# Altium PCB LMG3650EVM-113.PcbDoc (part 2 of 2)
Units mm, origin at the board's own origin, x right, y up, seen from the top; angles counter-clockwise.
Board outline 76.61 x 43.92 mm, 4 copper layers (Top Layer, Signal Layer 1, Signal Layer 2, Bottom Layer), stack 0.688 mm thick; 100 components, 58 nets, 255 pads, 761 vias.
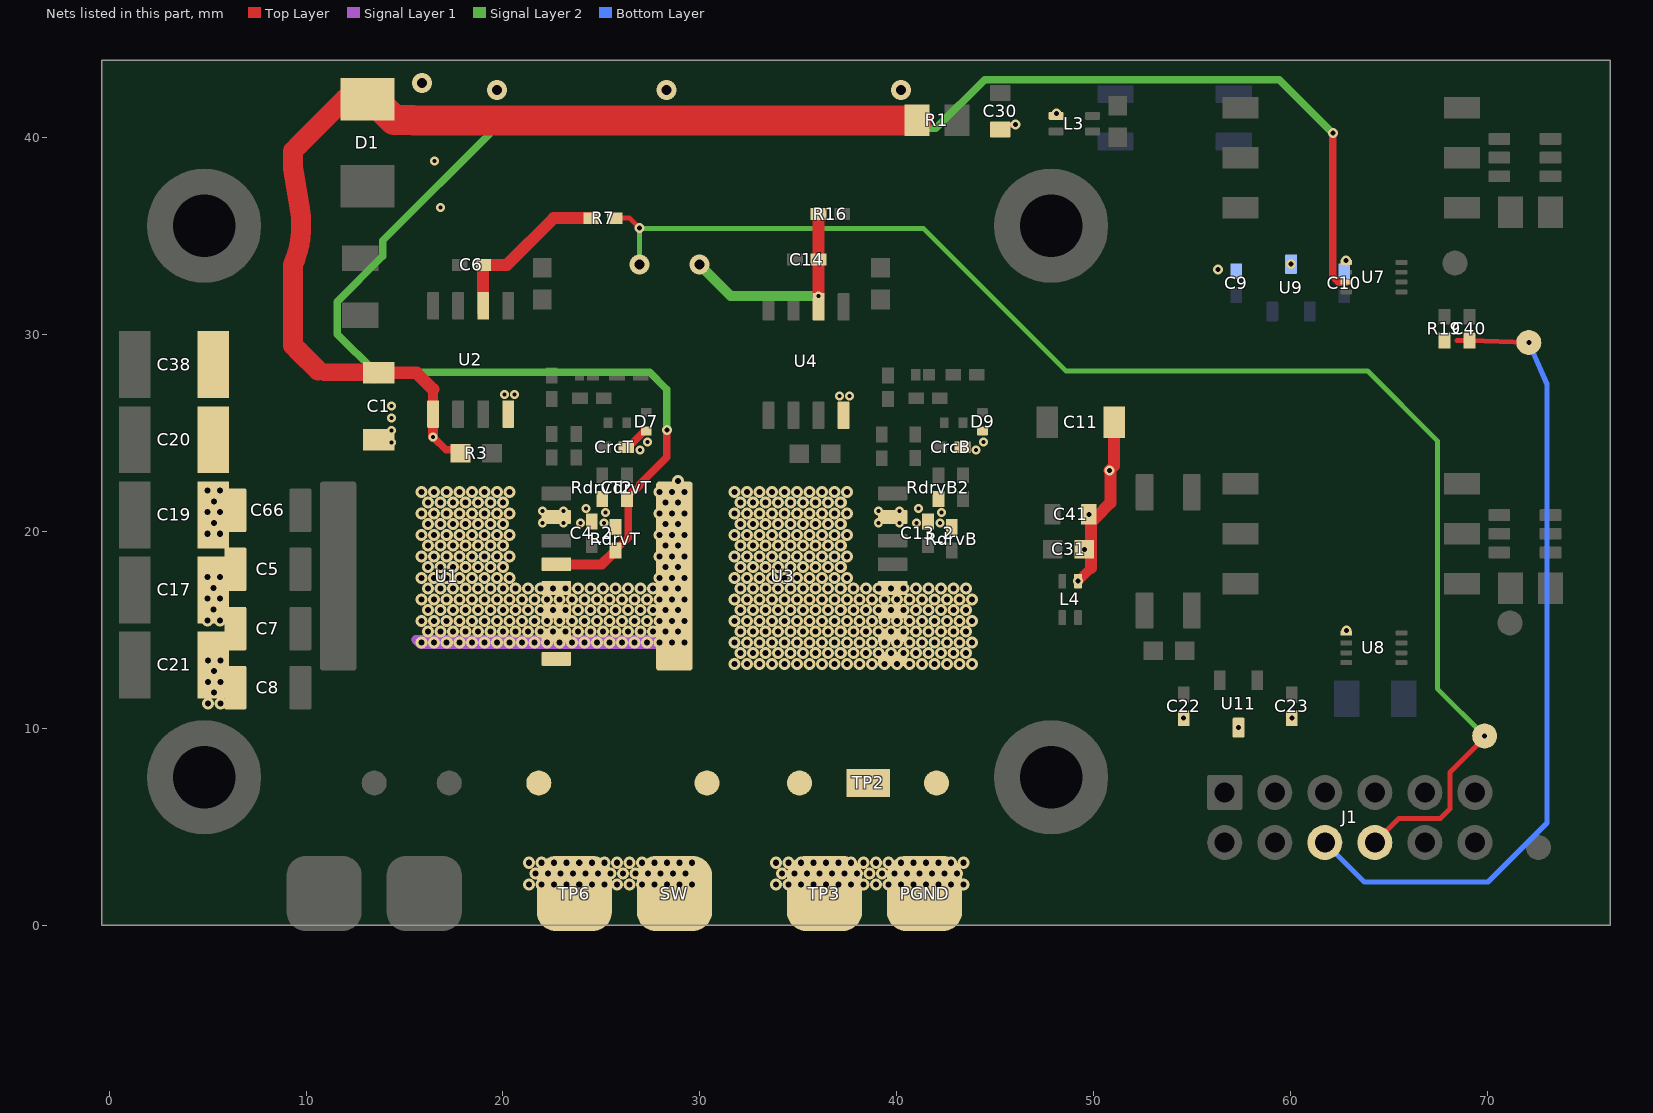
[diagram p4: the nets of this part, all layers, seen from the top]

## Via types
v1: diameter 0.61, hole 0.305, Top Layer to Bottom Layer, tented both sides, 665 vias
v2: diameter 0.508, hole 0.254, Top Layer to Bottom Layer, tented both sides, 47 vias
v3: diameter 0.457, hole 0.203, Top Layer to Bottom Layer, tented both sides, 41 vias
v4: diameter 1.016, hole 0.508, Top Layer to Bottom Layer, 8 vias

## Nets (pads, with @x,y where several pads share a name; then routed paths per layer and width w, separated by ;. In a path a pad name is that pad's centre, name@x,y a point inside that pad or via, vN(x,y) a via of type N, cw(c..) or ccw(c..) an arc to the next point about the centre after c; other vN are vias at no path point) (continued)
PGND: C5.1 C7.1 C8.1 C17.2 C19.2 C20.2 C21.2 C38.2 C66.1 pad.1@35.052,7.214 pad.1@42.012,7.214 PGND.1 TP2.1 TP3.1 U3.1 U3.2 U3.3 U3.4
  other v1: 33.85,2.071 34.485,2.071 35.12,2.071 35.755,2.071 36.39,2.071 37.025,2.071 37.66,2.071 38.295,2.071 38.93,2.071 39.565,2.071 40.2,2.071 40.835,2.071 41.47,2.071 42.105,2.071 42.74,2.071 43.375,2.071 34.167,2.617 34.802,2.617 35.437,2.617 36.072,2.617 36.707,2.617 37.342,2.617 37.977,2.617 38.612,2.617 39.247,2.617 39.882,2.617 40.517,2.617 41.152,2.617 41.787,2.617 42.422,2.617 43.057,2.617 33.85,3.163 34.485,3.163 35.12,3.163 35.755,3.163 36.39,3.163 37.025,3.163 37.66,3.163 38.295,3.163 38.93,3.163 39.565,3.163 40.2,3.163 40.835,3.163 41.47,3.163 42.105,3.163 42.74,3.163 43.375,3.163 5.015,11.257 5.65,11.257 5.333,11.804 5.015,12.35 5.65,12.35 5.333,12.896 31.75,13.259 32.385,13.259 33.02,13.259 33.655,13.259 34.29,13.259 34.925,13.259 35.56,13.259 36.195,13.259 36.83,13.259 37.465,13.259 38.1,13.259 38.735,13.259 39.37,13.259 40.005,13.259 40.64,13.259 41.275,13.259 41.91,13.259 42.545,13.259 43.18,13.259 43.815,13.259 5.015,13.442 5.65,13.442 32.067,13.805 32.703,13.805 33.337,13.805 33.972,13.805 34.608,13.805 35.242,13.805 35.877,13.805 36.512,13.805 37.148,13.805 37.782,13.805 38.417,13.805 39.052,13.805 39.688,13.805 40.322,13.805 40.957,13.805 41.593,13.805 42.227,13.805 42.862,13.805 43.497,13.805 31.75,14.351 32.385,14.351 33.02,14.351 33.655,14.351 34.29,14.351 34.925,14.351 35.56,14.351 36.195,14.351 36.83,14.351 37.465,14.351 38.1,14.351 38.735,14.351 39.37,14.351 40.005,14.351 40.64,14.351 41.275,14.351 41.91,14.351 42.545,14.351 43.18,14.351 43.815,14.351 32.067,14.897 32.703,14.897 33.337,14.897 33.972,14.897 34.608,14.897 35.242,14.897 35.877,14.897 36.512,14.897 37.148,14.897 37.782,14.897 38.417,14.897 39.052,14.897 39.688,14.897 40.322,14.897 40.957,14.897 41.593,14.897 42.227,14.897 42.862,14.897 43.497,14.897 31.75,15.443 32.385,15.443 33.02,15.443 33.655,15.443 34.29,15.443 34.925,15.443 35.56,15.443 36.195,15.443 36.83,15.443 37.465,15.443 38.1,15.443 38.735,15.443 39.37,15.443 40.005,15.443 40.64,15.443 41.275,15.443 41.91,15.443 42.545,15.443 43.18,15.443 43.815,15.443 4.987,15.475 5.622,15.475 32.067,15.989 32.703,15.989 33.337,15.989 33.972,15.989 34.608,15.989 35.242,15.989 35.877,15.989 36.512,15.989 37.148,15.989 37.782,15.989 38.417,15.989 39.052,15.989 39.688,15.989 40.322,15.989 40.957,15.989 41.593,15.989 42.227,15.989 42.862,15.989 43.497,15.989 5.305,16.021 31.75,16.535 32.385,16.535 33.02,16.535 33.655,16.535 34.29,16.535 34.925,16.535 35.56,16.535 36.195,16.535 36.83,16.535 37.465,16.535 38.1,16.535 38.735,16.535 39.37,16.535 40.005,16.535 40.64,16.535 41.275,16.535 41.91,16.535 42.545,16.535 43.18,16.535 43.815,16.535 4.987,16.567 5.622,16.567 32.067,17.081 32.703,17.081 33.337,17.081 33.972,17.081 34.608,17.081 35.242,17.081 35.877,17.081 36.512,17.081 37.148,17.081 37.782,17.081 38.417,17.081 39.052,17.081 39.688,17.081 40.322,17.081 40.957,17.081 41.593,17.081 42.227,17.081 42.862,17.081 43.497,17.081 5.305,17.113 31.75,17.628 32.385,17.628 33.02,17.628 33.655,17.628 34.29,17.628 34.925,17.628 35.56,17.628 36.195,17.628 36.83,17.628 37.465,17.628 4.987,17.659 5.622,17.659 32.067,18.174 32.703,18.174 33.337,18.174 33.972,18.174 34.608,18.174 35.242,18.174 35.877,18.174 36.512,18.174 37.148,18.174 31.75,18.72 32.385,18.72 33.02,18.72 33.655,18.72 34.29,18.72 34.925,18.72 35.56,18.72 36.195,18.72 36.83,18.72 37.465,18.72 32.067,19.266 32.703,19.266 33.337,19.266 33.972,19.266 34.608,19.266 35.242,19.266 35.877,19.266 36.512,19.266 37.148,19.266 31.75,19.812 32.385,19.812 33.02,19.812 33.655,19.812 34.29,19.812 34.925,19.812 35.56,19.812 36.195,19.812 36.83,19.812 37.465,19.812 5.004,19.866 5.639,19.866 32.067,20.358 32.703,20.358 33.337,20.358 33.972,20.358 34.608,20.358 35.242,20.358 35.877,20.358 36.512,20.358 37.148,20.358 5.321,20.412 31.75,20.904 32.385,20.904 33.02,20.904 33.655,20.904 34.29,20.904 34.925,20.904 35.56,20.904 36.195,20.904 36.83,20.904 37.465,20.904 5.004,20.958 5.639,20.958 32.067,21.45 32.703,21.45 33.337,21.45 33.972,21.45 34.608,21.45 35.242,21.45 35.877,21.45 36.512,21.45 37.148,21.45 5.321,21.504 31.75,21.996 32.385,21.996 33.02,21.996 33.655,21.996 34.29,21.996 34.925,21.996 35.56,21.996 36.195,21.996 36.83,21.996 37.465,21.996 5.004,22.05 5.639,22.05
PWM_H: C6.1 R7.2 U2.2 | length 8.9
  Top Layer w0.61: U2.2@18.994,31.101 18.994,33.51 20.197,33.51 22.574,35.887 R7.2@24.478,35.887
PWM_L: C14.2 R16.2 U4.2 | length 10.9
  Top Layer w0.61: v3(36.017,31.939) 36.017,35.077 36.022,35.077 R16.2@36.022,36.093
  Signal Layer 2 w0.508: v4(29.972,33.528) 31.561,31.939 v3(36.017,31.939)
S_PGND: C11.1 C13_2.2 C22.2 C23.2 C31.2 C41.2 CrcB.1 D9.2 L4.1 RdrvB2.1 RdrvB.1 U3.7 U4.8 U8.5 U11.3 | length 8.8
  Top Layer w0.483: v2(49.193,17.46) 49.859,18.126
  Top Layer w0.61: 49.859,18.126 49.859,20.461 50.086,20.688 50.837,21.439 v2@50.837,23.081 ; v2(50.798,23.081) 51.027,23.31 C11.1@51.027,25.527
  other v2: 57.343,10.027 54.559,10.5 60.046,10.5 62.811,14.961 49.517,19.075 49.744,20.853
  other v3: 39.064,20.425 40.134,20.425 40.994,20.422 42.188,20.422 42.264,20.955 39.064,21.031 40.134,21.031 41.091,21.152 44.015,24.116 44.394,24.515 37.093,26.87 37.601,26.87
S_SW: C1.2 C4_2.2 C9.2 C10.2 C30.2 CrcT.1 D7.2 L3.1 RdrvT2.1 RdrvT.1 U1.7 U2.8 U7.5 U9.3 | length 2.2
  Top Layer w0.254: C30.2@45.243,40.391 45.449,40.597 45.972,40.597 v2(46.021,40.646)
  Top Layer w0.381: CrcT.1@26.259,24.257 26.359,24.257 27.146,25.044 27.243,25.044 D7.2@27.277,25.079
  other v2: 56.304,33.286 60.01,33.553 62.789,33.747 48.097,41.2
  other v3: 21.996,20.425 23.067,20.425 23.927,20.422 25.121,20.422 25.197,20.955 21.996,21.031 23.067,21.031 24.206,21.138 26.948,24.116 14.335,24.493 27.326,24.515 14.335,25.112 14.335,25.732 14.335,26.351 20.066,26.924 20.574,26.924 16.834,36.436 16.533,38.789
  other v4: 19.692,42.393 28.312,42.393 40.197,42.393 15.896,42.756
SW: pad.1@21.819,7.214 pad.1@30.353,7.214 SW.1 TP6.1 U1.1 U1.2 U1.3 U1.4 U3.9 | length 27.8
  Signal Layer 1 w0.457: 15.572,14.497 15.826,14.243 16.943,14.243 17.858,14.243 18.772,14.243 19.636,14.243 20.525,14.243 21.439,14.243 22.303,14.243 23.192,14.243 24.106,14.243 24.97,14.243 25.859,14.243 26.722,14.243 27.611,14.243 28.475,14.243 29.364,14.243 29.11,14.497 28.907,14.497 15.572,14.497
  other v1: 21.332,2.071 21.967,2.071 22.602,2.071 23.237,2.071 23.872,2.071 24.507,2.071 25.142,2.071 25.777,2.071 26.412,2.071 27.047,2.071 27.682,2.071 28.317,2.071 28.952,2.071 29.587,2.071 21.649,2.617 22.284,2.617 22.919,2.617 23.554,2.617 24.189,2.617 24.824,2.617 25.459,2.617 26.094,2.617 26.729,2.617 27.364,2.617 27.999,2.617 28.634,2.617 29.269,2.617 21.332,3.163 21.967,3.163 22.602,3.163 23.237,3.163 23.872,3.163 24.507,3.163 25.142,3.163 25.777,3.163 26.412,3.163 27.047,3.163 27.682,3.163 28.317,3.163 28.952,3.163 29.587,3.163 15.875,14.351 16.51,14.351 17.145,14.351 17.78,14.351 18.415,14.351 19.05,14.351 19.685,14.351 20.32,14.351 20.955,14.351 21.59,14.351 22.225,14.351 22.86,14.351 23.495,14.351 24.13,14.351 24.765,14.351 25.4,14.351 26.035,14.351 26.67,14.351 27.305,14.351 27.94,14.351 28.575,14.351 29.21,14.351 16.192,14.897 16.828,14.897 17.462,14.897 18.098,14.897 18.732,14.897 19.367,14.897 20.002,14.897 20.637,14.897 21.273,14.897 21.907,14.897 22.543,14.897 23.177,14.897 23.812,14.897 24.447,14.897 25.082,14.897 25.717,14.897 26.352,14.897 26.987,14.897 27.622,14.897 28.258,14.897 28.892,14.897 15.875,15.443 16.51,15.443 17.145,15.443 17.78,15.443 18.415,15.443 19.05,15.443 19.685,15.443 20.32,15.443 20.955,15.443 21.59,15.443 22.225,15.443 22.86,15.443 23.495,15.443 24.13,15.443 24.765,15.443 25.4,15.443 26.035,15.443 26.67,15.443 27.305,15.443 27.94,15.443 28.575,15.443 29.21,15.443 16.192,15.989 16.828,15.989 17.462,15.989 18.098,15.989 18.732,15.989 19.367,15.989 20.002,15.989 20.637,15.989 21.273,15.989 21.907,15.989 22.543,15.989 23.177,15.989 23.812,15.989 24.447,15.989 25.082,15.989 25.717,15.989 26.352,15.989 26.987,15.989 27.622,15.989 28.258,15.989 28.892,15.989 15.875,16.535 16.51,16.535 17.145,16.535 17.78,16.535 18.415,16.535 19.05,16.535 19.685,16.535 20.32,16.535 20.955,16.535 21.59,16.535 22.225,16.535 22.86,16.535 23.495,16.535 24.13,16.535 24.765,16.535 25.4,16.535 26.035,16.535 26.67,16.535 27.305,16.535 27.94,16.535 28.575,16.535 29.21,16.535 16.192,17.081 16.828,17.081 17.462,17.081 18.098,17.081 18.732,17.081 19.367,17.081 20.002,17.081 20.637,17.081 21.273,17.081 21.907,17.081 22.543,17.081 23.177,17.081 23.812,17.081 24.447,17.081 25.082,17.081 25.717,17.081 26.352,17.081 26.987,17.081 27.622,17.081 28.258,17.081 28.892,17.081 15.875,17.628 16.51,17.628 17.145,17.628 17.78,17.628 18.415,17.628 19.05,17.628 19.685,17.628 20.32,17.628 27.94,17.628 28.575,17.628 29.21,17.628 16.192,18.174 16.828,18.174 17.462,18.174 18.098,18.174 18.732,18.174 19.367,18.174 20.002,18.174 28.258,18.174 28.892,18.174 15.875,18.72 16.51,18.72 17.145,18.72 17.78,18.72 18.415,18.72 19.05,18.72 19.685,18.72 20.32,18.72 27.94,18.72 28.575,18.72 29.21,18.72 16.192,19.266 16.828,19.266 17.462,19.266 18.098,19.266 18.732,19.266 19.367,19.266 20.002,19.266 28.258,19.266 28.892,19.266 15.875,19.812 16.51,19.812 17.145,19.812 17.78,19.812 18.415,19.812 19.05,19.812 19.685,19.812 20.32,19.812 27.94,19.812 28.575,19.812 29.21,19.812 16.192,20.358 16.828,20.358 17.462,20.358 18.098,20.358 18.732,20.358 19.367,20.358 20.002,20.358 28.258,20.358 28.892,20.358 15.875,20.904 16.51,20.904 17.145,20.904 17.78,20.904 18.415,20.904 19.05,20.904 19.685,20.904 20.32,20.904 27.94,20.904 28.575,20.904 29.21,20.904 16.192,21.45 16.828,21.45 17.462,21.45 18.098,21.45 18.732,21.45 19.367,21.45 20.002,21.45 28.258,21.45 28.892,21.45 15.875,21.996 16.51,21.996 17.145,21.996 17.78,21.996 18.415,21.996 19.05,21.996 19.685,21.996 20.32,21.996 27.94,21.996 28.575,21.996 29.21,21.996 28.892,22.543
Top_FET_FAULT: C40.1 J1.6 pad.1@72.078,29.575 R19.2 | length 41.6
  Top Layer w0.254: 68.428,29.667 C40.1@69.063,29.667 ; C40.1@69.063,29.677 v2(72.078,29.575)
  Bottom Layer w0.254: J1.6@61.722,4.191 63.729,2.184 70.004,2.184 73.002,5.183 73.002,27.453 v2(72.078,29.575)
Top_FET_FLT: CdrvT.2 RdrvT.2 U1.5 U7.7 | length 97.2
  Top Layer w0.381: RdrvT.2@25.716,19.015 25.826,19.124 25.826,19.224 25.911,19.224 26.359,19.673 26.359,21.563 CdrvT.2@26.289,21.633 26.399,21.743 26.399,21.843 26.646,22.09 26.731,22.09 26.932,22.291 26.932,22.376 28.315,23.759 v2(28.315,25.135) ; v2(62.128,40.208) 62.128,32.945 62.431,32.643 U7.7@62.811,32.643
  Top Layer w0.508: U1.5@22.711,18.315 25.017,18.315 25.57,18.869 25.67,18.869 25.716,18.915 RdrvT.2@25.716,19.015
  Signal Layer 2 w0.381: v2(28.315,25.135) 28.302,25.148 28.302,27.194 27.442,28.055 13.533,28.055 11.584,30.004 11.584,31.65 13.884,33.95 13.884,34.733 19.601,40.45 41.976,40.45 44.452,42.926 59.411,42.926 v2(62.128,40.208)
Top_FET_PWM: J1.8 pad.1@69.837,9.601 R7.1 | length 73.2
  Top Layer w0.254: R7.1@25.678,35.887 26.428,35.887 v2(26.919,35.396) ; J1.8@64.262,4.191 65.481,5.41 67.589,5.41 68.072,5.893 68.072,7.747 pad.1@69.882,9.557
  Signal Layer 2 w0.254: v2(26.919,35.396) 26.924,35.391 v4(26.924,33.528) ; v2@26.924,35.368 41.34,35.368 48.572,28.136 63.888,28.136 67.437,24.587 67.437,12.002 v2(69.837,9.601)
VGG_H: C1.1 D1.1 R1.2 R3.1 U2.5 | length 55
  Top Layer w0.254: D1.1@11.965,41.932 D1.1@13.114,41.932
  Top Layer w0.381: v3(16.459,24.776) 17.108,24.127 R3.1@17.818,24.127
  Top Layer w0.508: U2.5@16.454,26.274 16.454,27.197 ; v3(16.459,24.776) U2.5@16.459,26.269
  Top Layer w0.635: C1.1@13.473,27.821 C1.1@13.691,28.038 15.614,28.038 16.454,27.197
  Top Layer w0.889: 10.922,28.075 C1.1@13.473,28.075
  Top Layer w1.016: 10.615,28.151 9.632,29.133 9.335,29.431 9.335,33.501 ccw(c4.826,35.5) 9.692,36.306 9.335,38.461 9.335,39.302 9.632,39.6 D1.1@11.965,41.932
  Top Layer w1.524: D1.1@13.114,41.932 13.406,41.932 14.461,40.878 15.432,40.878 15.461,40.849 40.997,40.849 R1.2@41.018,40.87
pads on no net: H1.1 LBL1.0 U8.6

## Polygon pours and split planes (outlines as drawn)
ISO_RET_H_B on Bottom Layer "ISO_RET_H_B_L04_P144" (solid, pour order 144): 51.969,39.243 49.445,39.243 49.445,42.626 52.04,42.626 52.197,42.469 52.197,39.405
ISO_12V_H_B on Bottom Layer "ISO_12V_H_B_L04_P145" (solid, pour order 145): 51.969,39.37 49.445,39.37 49.445,42.875 51.918,42.875 52.197,42.596 52.197,39.532
S_PGND on Bottom Layer "S_PGND_L04_P161" (solid, remove dead copper, pour order 161): 31.141,27.331 32.545,28.735 44.671,28.735 44.671,17.783 38.003,17.783 38.003,22.53 31.141,22.53
S_SW on Bottom Layer "S_SW_L04_P164" (solid, remove dead copper, pour order 164): 12.32,27.764 13.346,28.789 27.026,28.789 29.717,28.789 29.717,23.587 28.506,23.587 27.026,22.107 27.026,17.932 21.158,17.932 21.158,22.53 12.32,22.53
AGND on Bottom Layer "AGND_L04_P166" (solid, remove dead copper, pour order 166): 64.516,8.382 55.118,8.382 54.102,7.366 54.102,5.258 54.102,0.94 54.61,0.432 74.6,0.432 75.692,1.524 75.692,43.155 75.311,43.536 67.97,43.536 67.564,43.129 67.564,34.29 65.202,31.928 65.202,28.931 65.024,28.753 65.024,8.89
SW on Bottom Layer "SW_L04_P168" (solid, remove dead copper, pour order 168): 29.718,22.715 29.394,23.322 28.704,23.413 27.191,21.9 27.191,17.794 21.006,17.768 21.053,22.555 12.32,22.5 12.32,10.804 29.718,10.804
PGND on Bottom Layer "PGND_L04_P173" (solid, remove dead copper, pour order 173): 44.196,23.308 31.141,23.308 31.141,0 44.196,0
AGND on Bottom Layer "AGND_L04_P178" (solid, remove dead copper, pour order 178): 15.596,30.277 16.18,33.334 23.444,38.125 40.716,38.125 40.716,30.277
S_PGND on Bottom Layer "S_PGND_L04_P189" (solid, pour order 189): 31.242,19.863 31.242,22.25 44.196,22.25 44.196,17.783 42.057,17.783 42.057,19.844
ISO_RET_L_B on Bottom Layer "ISO_RET_L_B_L04_P191" (solid, pour order 191): 48.198,16.006 49.559,16.006 51.359,17.805 54.229,17.805 54.839,17.196 55.55,17.196 55.778,16.967 55.778,13.36 55.562,13.144 49.721,13.144 48.198,14.667
S_PGND on Bottom Layer "S_PGND_L04_P200" (solid, pour order 200): 51.575,9.5 62.611,9.5 63.729,10.617 63.729,21.895 61.798,23.419 55.854,23.389 54.52,23.774 46.099,23.774 45.847,23.419 45.847,12.878
S_SW on Bottom Layer "S_SW_L04_P204" (solid, pour order 204): 58.29,30.704 63.729,30.704 63.729,40.716 60.153,43.539 45.009,43.463 45.009,38.537
S_SW on Bottom Layer "S_SW_L04_P208" (solid, remove dead copper, pour order 208): 11.092,31.937 11.171,29.72 12.32,27.764 14.175,28.354 14.175,33.954 22.603,39.468 45.023,39.468 58.29,30.704 63.729,30.704 63.729,40.716 60.153,43.539 19.809,43.539 12.194,35.924
AGND on Bottom Layer "AGND_L04_P209" (solid, remove dead copper, pour order 209): 48.145,26.543 52.096,26.543 52.832,25.808 62.655,25.808 65.048,23.06 69.621,25.781 69.621,29.041 65.048,30.277 62.655,28.973 49.86,29.052 40.67,38.274 23.444,38.125 16.18,33.334 15.596,30.277 45.339,30.37
S_SW on Signal Layer 2 "S_SW_L03_P203" (solid, pour order 203): 59.985,30.704 63.729,30.704 63.729,40.716 59.779,43.834 45.009,43.76 45.009,39.537
ISO_12V_H_B on Signal Layer 2 "ISO_12V_H_B_L03_P147" (solid, pour order 147): 51.969,39.243 49.445,39.243 49.445,42.748 51.918,42.748 52.197,42.469 52.197,39.405
ISO_RET_H_B on Signal Layer 2 "ISO_RET_H_B_L03_P135" (solid, pour order 135): 51.969,39.243 49.445,39.243 49.445,42.748 51.918,42.748 52.197,42.469 52.197,39.405
HVBUS on Signal Layer 2 "Signal Layer 2-HVBUS" (solid, remove dead copper, pour order 225): 8.026,0 18.847,0 18.847,9.829 11.047,9.829 11.047,23.139 8.303,23.139 5.81,24.672 4.361,29.058 0.229,29.058 0.229,10.287 8.026,10.287
SW on Signal Layer 2 "SW_L03_P175" (solid, remove dead copper, pour order 175): 29.718,22.715 29.394,23.322 28.704,23.413 27.191,21.9 27.191,17.794 21.016,17.767 21.016,22.5 12.32,22.5 12.32,10.287 29.718,10.287
5V on Signal Layer 2 "5V_L03_P205" (solid, remove dead copper, pour order 205): 47.481,26.956 47.868,26.568 52.07,26.568 52.832,25.808 62.655,25.808 66.091,23.139 70.079,26.123 65.735,29.483 63.615,29.496 49.321,29.584 40.842,38.093 23.444,38.125 16.18,33.334 15.596,30.277 44.819,30.277
S_SW on Signal Layer 2 "S_SW_L03_P207" (solid, remove dead copper, pour order 207): 14.565,34.22 22.603,39.49 47.371,39.49 58.29,30.704 63.729,30.704 63.729,40.716 60.153,43.539 12.093,43.316 8.508,39.731 8.508,22.573 14.565,22.546
S_SW on Signal Layer 2 "S_SW_L03_P165" (solid, remove dead copper, pour order 165): 12.32,27.764 13.346,28.789 27.026,28.789 29.717,28.789 29.717,23.587 28.506,23.587 27.026,22.107 27.026,17.932 21.016,17.932 21.016,22.5 12.32,22.5
5V on Signal Layer 2 "5V_L03_P167" (solid, remove dead copper, pour order 167): 65.888,2.464 65.532,2.819 65.532,8.484 65.126,8.89 65.126,28.677 67.589,31.14 67.589,37.846 68.529,38.786 75.184,38.786 75.819,38.151 75.819,7.315 70.968,2.464
S_PGND on Signal Layer 2 "S_PGND_L03_P198" (solid, pour order 198): 51.575,9.5 62.916,9.5 63.729,10.312 63.729,21.895 61.798,23.419 55.854,23.389 54.52,23.774 46.099,23.774 45.847,23.419 45.847,12.878
ISO_12V_L_B on Signal Layer 2 "ISO_12V_L_B_L03_P194" (solid, pour order 194): 48.198,16.006 49.559,16.006 51.359,17.805 54.229,17.805 54.839,17.196 55.55,17.196 55.778,16.967 55.778,13.36 55.562,13.144 49.721,13.144 48.198,14.667
S_PGND on Signal Layer 2 "S_PGND_L03_P157" (solid, remove dead copper, pour order 157): 31.141,27.331 32.545,28.735 44.222,28.735 46.191,23.77 46.177,17.783 38.003,17.783 38.003,22.516 31.141,22.516
PGND on Signal Layer 2 "PGND_L03_P177" (solid, remove dead copper, pour order 177): 44.196,23.308 31.141,23.308 31.141,0 44.196,0
ISO_RET_H_B on Signal Layer 1 "ISO_RET_H_B_L02_P062" (solid, pour order 62): 51.969,39.243 49.445,39.243 49.445,42.626 52.04,42.626 52.197,42.469 52.197,39.405
AGND on Signal Layer 1 "AGND_L02_P174" (solid, remove dead copper, pour order 174): 48.145,26.543 52.096,26.543 52.832,25.808 62.655,25.808 65.048,23.06 69.621,25.781 69.621,29.041 65.048,30.277 62.655,28.973 49.86,29.052 40.67,38.274 23.444,38.125 16.18,33.334 15.596,30.277 45.339,30.37
S_SW on Signal Layer 1 "S_SW_L02_P202" (solid, pour order 202): 14.159,38.543 15.106,39.49 45.023,39.468 58.29,30.704 63.729,30.704 63.729,40.716 60.153,43.539 12.093,43.316 8.508,39.731 8.508,22.573 14.159,22.548
S_SW on Signal Layer 1 "S_SW_L02_P134" (solid, remove dead copper, pour order 134): 12.32,27.764 13.346,28.789 27.026,28.789 29.717,28.789 29.717,23.587 28.506,23.587 27.026,22.107 27.026,17.932 21.016,17.932 21.016,22.555 12.32,22.555
AGND on Signal Layer 1 "AGND_L02_P149" (solid, remove dead copper, pour order 149): 65.024,8.89 64.516,8.382 55.118,8.382 54.102,7.366 54.102,5.258 54.102,0.94 54.61,0.432 74.6,0.432 75.692,1.524 75.692,43.155 75.311,43.536 67.97,43.536 67.564,43.129 67.564,34.29 65.024,31.75
ISO_12V_H_B on Signal Layer 1 "ISO_12V_H_B_L02_P066" (solid, pour order 66): 51.969,39.243 49.445,39.243 49.445,42.748 51.918,42.748 52.197,42.469 52.197,39.405
S_PGND on Signal Layer 1 "S_PGND_L02_P193" (solid, pour order 193): 51.575,9.5 62.611,9.5 63.729,10.617 63.729,21.895 61.798,23.419 55.854,23.389 53.464,24.079 46.314,24.079 45.847,23.419 45.847,12.878
PGND on Signal Layer 1 "PGND_L02_P187" (solid, remove dead copper, pour order 187): 44.196,22.39 31.141,22.39 31.141,0 44.196,0
PGND on Signal Layer 1 "PGND_L02_P172" (solid, remove dead copper, pour order 172): 44.196,23.308 31.141,23.308 31.141,10.653 44.196,10.654
PGND on Signal Layer 1 "PGND_L02_P152" (solid, remove dead copper, pour order 152): 15.487,13.847 30.014,14.123 31.141,17.175 31.141,23.244 44.196,23.244 44.196,11.873 41.874,9.55 3.505,9.55 3.505,22.25 4.735,23.481 7.606,23.481 14.731,16.356 14.946,14.327
S_PGND on Signal Layer 1 "S_PGND_L02_P148" (solid, remove dead copper, pour order 148): 31.141,27.331 32.545,28.735 44.602,28.735 46.921,23.754 46.838,17.783 38.003,17.783 38.003,22.555 31.141,22.555
ISO_RET_L_B on Signal Layer 1 "ISO_RET_L_B_L02_P132" (solid, pour order 132): 48.198,16.006 49.559,16.006 51.359,17.805 54.229,17.805 54.839,17.196 55.55,17.196 55.778,16.967 55.778,13.36 55.562,13.144 49.721,13.144 48.198,14.667
ISO_12V_L_B on Signal Layer 1 "ISO_12V_L_B_L02_P196" (solid, pour order 196): 48.198,16.006 49.559,16.006 51.359,17.805 54.229,17.805 54.839,17.196 55.55,17.196 55.778,16.967 55.778,13.36 55.562,13.144 49.721,13.144 48.198,14.667
SW on Signal Layer 1 "SW_L02_P162" (solid, remove dead copper, pour order 162): 29.718,22.715 29.394,23.322 28.704,23.413 27.191,21.9 27.191,17.794 21.016,17.767 21.016,22.5 15.138,22.5 15.138,13.767 29.718,13.767
ISO_RET_H_B on Top Layer "ISO_RET_H_B_L01_P150" (solid, pour order 150): 52.197,40.667 49.445,40.667 49.445,42.875 51.918,42.875 52.197,42.596
ISO_12V_H_B on Top Layer "ISO_12V_H_B_L01_P151" (solid, pour order 151): 51.969,39.37 49.445,39.37 49.445,40.492 52.197,40.492 52.197,39.532
HVBUS on Top Layer "HVBUS_L01_P182" (solid, remove dead copper, pour order 182): 2.286,30.759 0.432,30.759 0.432,10.617 1.555,10.617 2.286,11.802
NetRonB1_2 on Top Layer "NONET_L-01_P-001" (solid, pour order 224): 39.201,27.046 40.877,27.046 41.268,26.655 41.268,26.386 39.758,24.875 38.998,24.875 38.65,25.223 38.65,26.496
S_PGND on Top Layer "NONET_L-01_P-001" (solid, pour order 223): 37.932,25.435 37.932,27.098 37.652,27.378 37.078,27.378 36.789,27.109 36.789,25.337 37.173,24.953 37.519,24.953
NetDoffB_1 on Top Layer "NONET_L-01_P-001" (solid, pour order 222): 40.7,27.428 41.152,27.88 41.152,28.24 40.877,28.516 38.256,28.516 35.295,28.516 34.299,27.683 34.299,25.386 34.543,25.142 36.251,25.142 36.458,25.35 36.458,27.149 36.905,27.596 38.172,27.596 38.34,27.428
S_PGND on Top Layer "NONET_L-01_P-001" (solid, pour order 221): 43.766,25.277 44.192,25.277 44.642,24.826 44.642,24.204 44.267,23.829 43.126,23.829 42.927,24.028 42.927,24.464
IN_L on Top Layer "NONET_L-01_P-001" (solid, pour order 220): 39.076,21.565 40.512,21.565 40.918,21.971 40.918,22.592 42.527,24.128 42.527,24.457 42.628,25.278 42.628,25.768 42.217,25.768 41.462,24.776 41.084,24.128 39.247,24.128 38.937,23.779 38.937,21.708
S_PGND on Top Layer "S_PGND_L01_P219" (solid, remove dead copper, pour order 219): 39.202,21.401 40.503,21.401 41.806,22.053 42.381,22.053 42.836,21.598 43.088,20.615 43.088,19.815 42.484,19.815 42.048,20.041 39.12,20.041 38.835,20.244 38.835,21.224
S_SW on Top Layer "NONET_L-01_P-001" (solid, pour order 218): 26.698,25.277 27.124,25.277 27.575,24.826 27.575,24.204 27.2,23.829 26.058,23.829 25.859,24.028 25.859,24.464
IN_H on Top Layer "NONET_L-01_P-001" (solid, pour order 212): 22.008,21.565 23.444,21.565 23.851,21.971 23.851,22.592 25.459,24.128 25.459,24.457 25.561,25.278 25.561,25.768 25.149,25.768 24.395,24.776 24.016,24.128 22.179,24.128 21.869,23.779 21.869,21.708
NetRonT1_2 on Top Layer "NONET_L-01_P-001" (solid, pour order 217): 22.133,27.046 23.809,27.046 24.201,26.655 24.201,26.386 22.69,24.875 21.931,24.875 21.583,25.223 21.583,26.496
S_SW on Top Layer "NONET_L-01_P-001" (solid, pour order 215): 20.904,25.49 20.904,27.153 20.625,27.432 20.05,27.432 19.761,27.163 19.761,25.392 20.145,25.008 20.491,25.008
S_SW on Top Layer "S_SW_L01_P214" (solid, remove dead copper, pour order 214): 22.135,21.401 23.435,21.401 24.739,22.053 25.314,22.053 25.768,21.598 26.021,20.615 26.021,19.815 25.416,19.815 24.981,20.041 22.052,20.041 21.768,20.244 21.768,21.224
NetDoffT_1 on Top Layer "NONET_L-01_P-001" (solid, pour order 216): 23.672,27.483 24.125,27.935 24.125,28.295 23.849,28.57 21.229,28.57 18.268,28.57 17.272,27.738 17.272,25.441 17.516,25.197 19.224,25.197 19.431,25.404 19.431,27.203 19.878,27.65 21.145,27.65 21.312,27.483
S_SW on Top Layer "S_SW_L01_P143" (solid, remove dead copper, pour order 143): 15.648,28.575 16.859,24.054 9.017,24.054 9.017,27.178 10.414,28.575
S_PGND on Top Layer "S_PGND_L01_P211" (solid, remove dead copper, pour order 211): 45.834,25.096 47.107,26.368 51.559,26.368 51.841,26.086 51.841,24.257 52.952,23.146 52.415,22.609 45.853,22.609
AGND on Top Layer "AGND_L01_P210" (solid, remove dead copper, pour order 210): 64.516,8.382 55.118,8.382 54.102,7.366 54.102,5.258 54.102,0.94 54.61,0.432 74.6,0.432 75.692,1.524 75.692,43.155 75.311,43.536 67.97,43.536 67.564,43.129 67.564,34.29 65.202,31.928 65.202,28.931 65.024,28.753 65.024,8.89
S_SW on Top Layer "S_SW_L01_P206" (solid, remove dead copper, pour order 206): 15.135,40.107 47.447,40.107 56.85,30.704 63.729,30.704 63.729,40.716 59.951,43.699 15.135,43.491
AGND on Top Layer "AGND_L01_P176" (solid, remove dead copper, pour order 176): 16.18,30.328 16.18,33.334 23.444,38.125 39.903,38.227 39.903,30.328
S_SW on Top Layer "S_SW_L01_P195" (solid, pour order 195): 48.201,39.175 56.672,30.704 63.729,30.704 63.729,40.716 60.153,43.539 45.009,43.463 45.009,38.537
S_PGND on Top Layer "S_PGND_L01_P192" (solid, pour order 192): 51.575,9.5 62.611,9.5 63.729,10.617 63.729,21.895 61.305,23.808 46.123,23.808 45.847,23.419 45.847,12.878
SW on Top Layer "SW_L01_P190" (solid, remove dead copper, pour order 190): 31.064,22.606 18.898,22.606 18.898,-0.025 31.064,-0.025
SW on Top Layer "SW_L01_P169" (solid, remove dead copper, pour order 169): 29.718,22.715 29.394,23.322 28.704,23.413 27.191,21.9 27.191,17.94 20.985,17.94 20.985,23.308 15.003,23.308 15.003,10.804 29.718,10.804
ISO_RET_L_B on Top Layer "ISO_RET_L_B_L01_P158" (solid, pour order 158): 48.198,16.006 49.559,16.006 51.359,17.805 54.229,17.805 54.839,17.196 55.55,17.196 55.778,16.967 55.778,13.36 55.562,13.144 49.721,13.144 48.198,14.667
HVBUS on Top Layer "HVBUS_L01_P184" (solid, remove dead copper, pour order 184): 18.875,9.884 14.095,10.325 14.095,22.631 8.484,22.631 8.484,0 18.847,0
PGND on Top Layer "PGND_L01_P171" (solid, remove dead copper, pour order 171): 44.196,23.308 31.242,23.308 31.231,11.003 32.782,7.173 32.782,0 44.196,0
PGND on Top Layer "PGND_L01_P181" (solid, remove dead copper, pour order 181): 7.112,30.759 4.242,30.759 4.242,10.617 7.112,10.617
HVBUS on Top Layer "HVBUS_L01_P159" (solid, remove dead copper, pour order 159): 12.548,22.504 8.837,22.504 8.837,10.109 12.548,10.109

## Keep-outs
Keep-Out Layer:
  lines w0.254: -1.524,-0.127 -1.524,44.069 ; -1.401,-0.127 6.337,-0.127 ; -1.401,44.069 76.352,44.069 76.352,0
  text ".Layer_Name" at 12.751,-35.478 h0.76

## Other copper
Top Layer:
  rectangle net Top_FET_FAULT: 67.462,29.235 69.393,30.124
  region net S_SW: 63.113,34.061 62.503,34.061 62.503,33.503 63.113,33.503
  rectangle net 5V_T: 62.509,31.725 63.119,32.283
  rectangle net 5V: 65.278,12.649 65.989,13.487
  rectangle net ISO_12V_L_B: 48.198,15.005 48.793,16.006
  rectangle net 5V: 19.964,30.328 22.687,32.334
  rectangle net SW: 14.986,17.805 21.047,23.308
  rectangle net 5V: 37.414,30.455 39.7,32.283
Bottom Layer:
  rectangle net NetD3_3: 56.185,41.123 58.014,42.748
  rectangle net 5V: 19.071,30.524 20.726,31.482

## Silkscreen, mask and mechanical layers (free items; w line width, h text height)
Top Overlay:
  lines w0.127: 25.018,34.485 25.388,34.115 ; 25.963,33.569 ccw(c25.4,33.528) 25.965,33.53 ; 26.479,32.533 26.869,32.923 ; 27.487,33.569 ccw(c26.924,33.528) 27.489,33.53 ; 28.486,34.098 28.876,34.488 ; 29.011,33.569 ccw(c28.448,33.528) 29.013,33.53 ; 30.009,32.934 30.507,32.436 ; 30.535,33.569 ccw(c29.972,33.528) 30.537,33.53
  lines w0.254: 0.483,10.552 0.483,35.063 44.964,35.063 44.964,10.552 0.483,10.552
  text "LMG3650EVM-113" at 21.179,36.87 h1.02
  text "AGND" at 22.949,34.305 h0.76
  text "VCC_5V" at 28.89,34.163 h0.76
  text "PWM_H" at 25.155,31.693 h0.76
  text "PWM_L" at 29.384,31.693 h0.76
  text "Danger High Voltage" at 9.087,8.389 h1.02
  text "Max DC Input:  / 520 V/25 A" at -0.33,1.727 h1.52
Bottom Overlay:
  lines w0.254: 5.055,10.552 44.971,10.552 44.971,35.063 5.055,35.063 5.055,10.552
  text "Max DC Input:  / 520 V/25 A" at 23.139,3.2 h0.76
Top Paste:
  text ".Layer_Name" at 129.362,74.638 h0.76
Bottom Paste:
  text ".Layer_Name" at 129.362,74.638 h0.76
Top Solder:
  text ".Layer_Name" at 129.362,74.638 h0.76
Bottom Solder:
  region: 41.299,10.757 44.791,12.81 43.84,14.429 40.347,12.375
  rectangle: 11.998,10.755 41.3,13.582
  rectangle: 11.994,12.801 44.788,29.066
  text ".Layer_Name" at 129.362,74.638 h0.76
M1 Board Outline:
  lines w0.254: -0.381,0 76.225,0 76.225,43.917 -0.381,43.917 -0.381,0 ; 5.055,10.552 44.967,10.552 44.967,35.063 5.055,35.063 5.055,10.552
  text ".Layer_Name" at 12.751,-35.478 h0.76
M2 Board Dimensions:
  rectangle: -1.778,-20.911 1.397,-17.736
  rectangle: 1.27,-24.099 10.795,-20.924
  lines w0.178: -1.905,-17.749 -1.905,-24.099 23.495,-24.099 23.495,-17.749 ; -1.778,-20.911 23.622,-20.911 ; -1.778,-17.736 23.622,-17.736 ; 1.27,-24.099 1.27,-17.749 ; 4.445,-24.099 4.445,-17.749 ; 10.795,-24.099 10.795,-17.749 ; 17.145,-24.099 17.145,-17.749
  lines w0.254: -0.381,0 76.225,0 76.225,43.917 -0.381,43.917 -0.381,0 ; 5.055,10.552 44.956,10.552 44.956,35.063 5.055,35.063 5.055,10.552
  text ".Layer_Name" at 12.751,-35.478 h0.76
M3 3D STEP Top:
  lines w0.254: 1.403,4.173 1.403,38.873 51.134,38.873 51.134,4.173 1.403,4.173
  text ".Layer_Name" at 12.751,-35.478 h0.76
M4 3D STEP Bottom:
  lines w0.254: 0,0 76.225,0 76.225,39.001 0,39.001 0,0 ; 13.31,14.834 39.37,14.834 39.37,28.6 13.31,28.6 13.31,14.834
M5 Assembly Top:
  lines w0.254: -9.322,-37.298 158.318,-37.298 ; -9.322,-32.134 158.369,-32.134 ; -9.322,-26.969 -9.322,-42.463 92.405,-42.463 158.369,-42.463 158.369,-26.969 -9.309,-26.969 -9.309,-42.463 ; 53.289,-42.463 53.289,-26.969 ; 85.471,-32.134 85.471,-26.969 ; 106.807,-32.134 106.807,-26.969 ; 107.302,67.653 147.32,67.653 ; 122.606,-42.628 122.606,-37.476
  text "PCB VIEWED FROM TOP SIDE" at 108.902,79.79 h0.76
  text "IGNORE ->" at 108.902,74.638 h0.76
  text "PLOT NAME =" at 108.902,69.41 h0.76
  text "COMPONENTS MARKED 'DNP' SHOULD NOT BE POPULATED." at 27.394,-21.762 h0.76
  text "ASSEMBLY VARIANT:" at 27.381,-24.696 h0.76
  text ".VariantName" at 53.696,-24.696 h0.76
  text "BOARD #:" at 55.194,-30.326 h0.76
  text ".PRJ_Number" at 69.05,-30.326 h0.76
  text "REV:" at 90.5,-30.326 h0.76
  text "A3" at 97.904,-30.326 h0.76
  text "SVN REV:" at 111.785,-30.326 h0.76
  text ".VersionControl_RevNumber" at 124.638,-30.326 h0.76
  text ".plot_File_Name" at 12.751,-40.706 h0.76
  text "GENERATED    :" at 55.245,-40.706 h0.76
  text ".Print_Date" at 77.33,-40.706 h0.76
  text ".Print_Time" at 95.847,-40.706 h0.76
  text "TEXAS INSTRUMENTS" at 127.965,-40.706 h0.76
M6 Assembly Bottom:
  lines w0.254: -9.335,-32.146 158.356,-32.146 ; -9.284,-37.311 158.356,-37.311 ; 42.227,-32.146 42.227,-26.982 ; 63.563,-32.146 63.563,-26.982 ; 95.745,-42.476 95.745,-26.982 ; 118.326,-42.476 158.344,-42.476 158.344,-26.982 -9.335,-26.982 -9.335,-42.476 56.629,-42.476 158.356,-42.476 158.356,-26.982 ; 143.04,67.475 143.04,72.627
  text ".VersionControl_RevNumber" at 141.008,79.777 h0.76
  text "TEXAS INSTRUMENTS" at 137.681,69.397 h0.76
  text "COMPONENTS MARKED 'DNP' SHOULD NOT BE POPULATED." at 170.79,-21.851 h0.76
  text ".VariantName" at 144.272,-24.797 h0.76
  text "ASSEMBLY VARIANT:" at 170.663,-24.797 h0.76
  text "SVN REV:" at 37.249,-30.339 h0.76
  text "A3" at 51.13,-30.339 h0.76
  text "REV:" at 58.534,-30.339 h0.76
  text ".PRJ_Number" at 79.985,-30.339 h0.76
  text "BOARD #:" at 93.84,-30.339 h0.76
  text "PCB VIEWED FROM BOTTOM SIDE" at 156.743,-30.339 h0.76
  text "IGNORE ->" at 62.81,-35.478 h0.76
  text ".Print_Time" at 53.188,-40.719 h0.76
  text ".Print_Date" at 71.704,-40.719 h0.76
  text "GENERATED    :" at 93.789,-40.719 h0.76
  text ".plot_File_Name" at 136.284,-40.719 h0.76
  text "PLOT NAME =" at 156.743,-40.719 h0.76
M9 Title Sheet:
  drawing of 57 lines, arcs and shapes, not listed
  text "1" at 16.887,190.455 h0.76
  text "2" at 80.277,190.455 h0.76
  text "3" at 143.506,190.455 h0.76
  text "4" at 207.175,190.455 h0.76
  text "5" at 270.65,190.455 h0.76
  text "6" at 334.277,190.455 h0.76
  text "A" at -12.484,161.423 h0.76
  text "A" at 363.436,161.423 h0.76
  text "B" at -12.484,100.971 h0.76
  text "B" at 363.436,100.971 h0.76
  text "1" at 133.498,64.351 h0.76
  text "C" at 363.436,40.646 h0.76
  text "PROJECT TITLE:" at 286.22,-6.624 h0.76
  text "Sunliner EVM" at 287.49,-10.01 h0.76
  text "DESIGNED FOR:" at 286.22,-14.269 h0.76
  text ".PRJ_Customer" at 287.49,-17.825 h0.76
  text "D" at -12.484,-19.552 h0.76
  text "D" at 363.436,-19.552 h0.76
  text "FILE NAME:" at 286.22,-21.889 h0.76
  text ".PCB_File_Name_No_Path" at 287.49,-24.937 h0.76
  text "Texas Instruments (TI) and/or its licensors do not warrant the accuracy or completeness of this specification" at 159.995,-29.048 h0.76
  text "ENGINEER:" at 286.22,-29.255 h0.76
  text "LAYOUT BY:" at 324.447,-29.255 h0.76
  text "or any information contained therein. TI and/or its licensors do not warrant that this design will meet" at 158.852,-31.909 h0.76
  text "Kyle Wolf" at 287.49,-33.192 h0.76
  text "Kyle Wolf" at 325.73,-33.192 h0.76
  text "the specifications, will be suitable for your application or fit for any particular purpose, or will operate in" at 158.852,-34.771 h0.76
  text ".Layer_Name" at 12.751,-35.478 h0.76
  text "ALTIUM DESIGNER VERSION:" at 324.447,-37.129 h0.76
  text "an implementation. TI and/or its licensors do not warrant that the design is production worthy. You should" at 158.852,-37.633 h0.76
  text "completely validate and test your design implementation to confirm the system functionality for your application." at 159.995,-40.495 h0.76
  text ".print_Scale" at 287.49,-40.516 h0.76
  text ".Application_BuildNumber" at 325.73,-40.516 h0.76
  text "2" at 80.277,-45.765 h0.76
  text "3" at 143.506,-45.765 h0.76
  text "4" at 207.175,-45.765 h0.76
  text "5" at 270.65,-45.765 h0.76
  text "6" at 334.277,-45.765 h0.76
M10 Fab Notes:
  drawing of 185 lines, arcs and shapes, not listed
  text "DESIGN INFORMATION" at 312.573,136.442 h0.76
  text "MIN. TRACK WIDTH:" at 296.201,131.87 h0.76
  text "6" at 324.046,131.87 h0.76
  text "MIL" at 327.976,131.87 h0.76
  text "MIN. CLEARANCE:" at 296.201,128.517 h0.76
  text "5.5" at 322.522,128.517 h0.76
  text "MIL" at 327.976,128.517 h0.76
  text "MIN. VIA PAD SIZE:" at 296.201,125.164 h0.76
  text "16" at 323.284,125.164 h0.76
  text "MIL" at 327.976,125.164 h0.76
  text "4 MIL" at 313.854,121.565 h0.76
  text "MINIMUM ANNULAR RING" at 287.839,121.456 h0.76
  text "PER" at 292.919,118.459 h0.76
  text "IPC-D-275 CLASS 2 LEVEL C" at 298.507,118.459 h0.76
  text "MIL, HOLES" at 336.308,115.607 h0.76
  text "+/-" at 326.339,115.588 h0.76
  text "+/-" at 348.031,115.588 h0.76
  text "REGISTRATION TOLERANCES:" at 287.839,115.461 h0.76
  text "METAL" at 318.313,115.461 h0.76
  text "MIL" at 357.059,115.461 h0.76
  text "MATERIAL:" at 285.939,110.141 h0.76
  text "FR-4 High Tg" at 310.995,106.577 h0.76
  text "FR-408" at 296.633,106.359 h0.76
  text "X" at 307.098,106.359 h0.76
  text "OTHER" at 334.428,106.359 h0.76
  text "X" at 301.687,102.422 h0.76
  text "78.7 MIL (2.0 mm) +/-10%" at 304.763,102.226 h0.76
  text "THICKNESS:" at 287.839,102.117 h0.76
  text "OTHER" at 337.4,102.117 h0.76
  text "TOLERANCE:" at 287.839,98.104 h0.76
  text "X" at 309.157,98.104 h0.76
  text "ANSI IPC-6012 TYPE 3 CLASS 2" at 313.905,98.104 h0.76
  text "OTHER +/-" at 313.905,94.142 h0.76
  text "BOW & TWIST:" at 287.839,90.154 h0.76
  text "X" at 309.157,90.154 h0.76
  text "ANSI IPC-6012 TYPE 3 CLASS 2" at 313.905,90.154 h0.76
  text "OTHER +/-" at 313.905,86.128 h0.76
  text "DRILLING:" at 285.939,82.61 h0.76
  text "REFERENCE:" at 287.839,79.638 h0.76
  text "X" at 304.304,79.638 h0.76
  text "AS SHOWN" at 309.053,79.638 h0.76
  text "X" at 327.189,79.638 h0.76
  text "NC_DRILL FILES" at 330.669,79.638 h0.76
  text "PTH MIN COPPER THICKNESS:" at 287.839,75.625 h0.76
  text "X" at 321.931,75.625 h0.76
  text "1MIL" at 325.614,75.625 h0.76
  text "OTHER" at 338.238,75.625 h0.76
  text "BOARD FINISH:" at 285.939,71.586 h0.76
  text "SILKSCREEN:" at 289.882,68.589 h0.76
  text "X" at 313.981,68.589 h0.76
  text "TOP" at 317.181,68.589 h0.76
  text "X" at 326.935,68.589 h0.76
  text "BOTTOM" at 330.161,68.589 h0.76
  text "SILKSCREEN COLOR:" at 289.882,64.347 h0.76
  text "X" at 313.955,64.347 h0.76
  text "WHITE" at 317.181,64.347 h0.76
  text "OTHER" at 330.161,64.347 h0.76
  text "SOLDER RESIST COLOR:" at 289.882,60.029 h0.76
  text "X" at 304.303,55.986 h0.76
  text "GREEN" at 307.529,55.986 h0.76
  text "BLUE" at 322.541,55.986 h0.76
  text "OTHER" at 336.206,55.986 h0.76
  text "IMMERSION GOLD (ENIG)" at 312.889,51.197 h0.76
  text "ENEPIG" at 346.862,51.114 h0.76
  text "SURFACE FINISH:" at 285.939,51.089 h0.76
  text "X" at 308.14,51.089 h0.76
  text "IMM. TIN/SILVER OR EQUIV" at 294.31,47.101 h0.76
  text "OTHER" at 330.669,47.101 h0.76
  text "X" at 308.204,42.748 h0.76
  text "ARRAY/PANEL:" at 285.939,42.554 h0.76
  text "CUT AND TRIM PER MECH LAYER 1" at 312.889,42.445 h0.76
  text "N.C. ROUTE" at 312.889,38.592 h0.76
  text "V. SCORE" at 334.885,38.592 h0.76
  text "CERTIFICATION:" at 285.939,35.112 h0.76
  text "MATERIALS AND WORKMANSHIP FOR ALL PCBS" at 304.354,35.112 h0.76
  text "TO MEET OR EXCEED THE REQUIREMENTS OF:" at 304.354,32.623 h0.76
  text "X" at 294.868,29.156 h0.76
  text "ANSI IPC-A-600F CLASS ->" at 298.398,29.156 h0.76
  text "X" at 340.03,29.156 h0.76
  text "2" at 343.051,29.156 h0.76
  text "1" at 335.05,29.118 h0.76
  text "3" at 352.043,29.118 h0.76
  text "X" at 294.92,25.104 h0.76
  text "UL 94V-0" at 298.398,25.104 h0.76
  text "X" at 315.545,25.104 h0.76
  text "RoHS" at 319.023,25.104 h0.76
  text "OTHER" at 335.391,25.104 h0.76
  text "PER ORDER" at 345.476,25.104 h0.76
  text "ADDITIONAL REQUIREMENTS:" at 285.939,21.523 h0.76
  text "MICROSECTION:" at 287.839,18.602 h0.76
  text "YES" at 310.844,18.602 h0.76
  text "REQUIRED" at 332.726,14.636 h0.76
  text "BARE BOARD ELEC. TEST:" at 287.839,14.563 h0.76
  text "NONE" at 321.004,14.563 h0.76
  text "X" at 329.5,14.563 h0.76
  text "PER ORDER" at 347.763,14.563 h0.76
  text "MANUFACTURER'S UL:" at 287.839,10.576 h0.76
  text "RAIL" at 317.448,10.467 h0.76
  text "METAL" at 329.94,10.467 h0.76
  text "X" at 339.471,10.458 h0.76
  text "SILK" at 342.937,10.467 h0.76
  text ".Layer_Name" at 12.751,-35.478 h0.76
M11 Gerber Information:
  lines w0.254: -9.322,-37.298 158.318,-37.298 ; -9.322,-32.134 158.369,-32.134 ; -9.322,-26.969 -9.322,-42.463 92.405,-42.463 158.369,-42.463 158.369,-26.969 -9.309,-26.969 -9.309,-42.463 ; 53.289,-42.463 53.289,-26.969 ; 85.471,-32.134 85.471,-26.969 ; 106.807,-32.134 106.807,-26.969 ; 107.302,67.653 147.32,67.653 ; 122.606,-42.628 122.606,-37.476
  text "PLOT NAME =" at 108.902,69.41 h0.76
  text "BOARD #:" at 55.194,-30.326 h0.76
  text ".PRJ_Number" at 69.05,-30.326 h0.76
  text "REV:" at 90.5,-30.326 h0.76
  text "A3" at 97.904,-30.326 h0.76
  text "SVN REV:" at 111.785,-30.326 h0.76
  text ".VersionControl_RevNumber" at 124.638,-30.326 h0.76
  text ".plot_File_Name" at 12.751,-40.706 h0.76
  text "GENERATED    :" at 55.245,-40.706 h0.76
  text ".Print_Date" at 77.33,-40.706 h0.76
  text ".Print_Time" at 95.847,-40.706 h0.76
  text "TEXAS INSTRUMENTS" at 127.965,-40.706 h0.76
M12 Stackup:
  drawing of 295 lines, arcs and shapes, not listed
  text "Layer" at 242.642,181.209 h1.52
  text "Name" at 253.054,181.209 h1.52
  text "Material" at 276.923,181.209 h1.52
  text "Thickness" at 298.762,181.209 h1.52
  text "Constant" at 315.267,181.209 h1.52
  text "Board Layer Stack" at 329.742,181.209 h1.52
  text "Top Overlay" at 253.054,178.161 h1.52
  text "Top Solder" at 253.054,175.113 h1.52
  text "Solder Resist" at 276.923,175.113 h1.52
  text "0.40mil" at 298.762,175.113 h1.52
  text "3.5" at 315.267,175.113 h1.52
  text "1" at 242.642,172.065 h1.52
  text "Top Layer" at 253.054,172.065 h1.52
  text "2.80mil" at 298.762,172.065 h1.52
  text "Dielectric 1" at 253.054,169.017 h1.52
  text "FR-4" at 276.923,169.017 h1.52
  text "4.60mil" at 298.762,169.017 h1.52
  text "4.2" at 315.267,169.017 h1.52
  text "2" at 242.642,165.969 h1.52
  text "Signal Layer 1" at 253.054,165.969 h1.52
  text "2.80mil" at 298.762,165.969 h1.52
  text "Dielectric 2" at 253.054,162.921 h1.52
  text "FR-4" at 276.923,162.921 h1.52
  text "6.69mil" at 298.762,162.921 h1.52
  text "4.2" at 315.267,162.921 h1.52
  text "3" at 242.642,159.873 h1.52
  text "Signal Layer 2" at 253.054,159.873 h1.52
  text "2.80mil" at 298.762,159.873 h1.52
  text "Dielectric 3" at 253.054,156.825 h1.52
  text "FR-4" at 276.923,156.825 h1.52
  text "4.60mil" at 298.762,156.825 h1.52
  text "4.2" at 315.267,156.825 h1.52
  text "4" at 242.642,153.777 h1.52
  text "Bottom Layer" at 253.054,153.777 h1.52
  text "2.80mil" at 298.762,153.777 h1.52
  text "Bottom Solder" at 253.054,150.729 h1.52
  text "Solder Resist" at 276.923,150.729 h1.52
  text "0.40mil" at 298.762,150.729 h1.52
  text "3.5" at 315.267,150.729 h1.52
  text "Bottom Overlay" at 253.054,147.681 h1.52
  text ".Layer_Name" at 129.362,74.638 h0.76
M13 Component Bodies Top:
  text ".Layer_Name" at 12.751,-35.478 h0.76
M14 Component Bodies Bottom:
  text ".Layer_Name" at 12.751,-35.478 h0.76
M15 Courtyards Top:
  text ".Layer_Name" at 12.751,-35.478 h0.76
M16 Courtyards Bottom:
  text ".Layer_Name" at 12.751,-35.478 h0.76
Drill Drawing:
  circle w0.254: c96.142,11.762 r0.847
  lines w0.254: 95.296,16.418 96.989,16.418 96.142,14.725 95.296,16.418 ; 95.296,18.958 95.719,18.958 95.719,18.535 96.566,18.535 96.566,18.958 96.989,18.958 96.989,19.805 96.566,19.805 96.566,20.228 95.719,20.228 95.719,19.805 95.296,19.805 95.296,18.958 ; 95.296,22.345 96.989,22.345 96.989,24.038 95.296,24.038 95.296,22.345 ; 95.296,26.155 95.296,26.578 95.719,27.002 95.296,27.425 95.296,27.848 95.719,27.848 96.142,27.425 96.566,27.848 96.989,27.848 96.989,27.425 96.566,27.002 96.989,26.578 96.989,26.155 96.566,26.155 96.142,26.578 95.719,26.155 95.296,26.155 ; 95.296,30.388 95.719,30.388 96.142,29.965 96.566,30.388 96.989,30.388 96.566,30.812 96.989,31.235 96.566,31.235 96.142,31.658 95.719,31.235 95.296,31.235 95.719,30.812 95.296,30.388
  lines w0.305: 93.777,9.772 247.506,9.772 ; 93.777,32.632 247.506,32.632 ; 107.769,5.962 107.769,36.442 ; 123.97,5.962 123.97,36.442 ; 158.148,5.962 158.148,36.442 ; 170.998,5.962 170.998,36.442 ; 189.636,5.962 189.636,36.442 ; 227.725,5.962 227.725,36.442 ; 93.777,5.962 247.506,5.962 247.506,36.442 93.777,36.442 93.777,5.962
  text ".Layer_Name" at 129.362,74.638 h0.76
  text "Symbol" at 96.063,33.775 h1.83
  text "Quantity" at 108.912,33.775 h1.83
  text "Finished Hole Size" at 125.113,33.775 h1.83
  text "Plated" at 159.291,33.775 h1.83
  text "Hole Type" at 172.141,33.775 h1.83
  text "Drill Layer Pair" at 190.779,33.775 h1.83
  text "Tolerance" at 228.868,33.775 h1.83
  text "41" at 108.912,29.965 h1.52
  text "8.00mil (0.203mm)" at 125.113,29.965 h1.52
  text "PTH" at 159.291,29.965 h1.52
  text "Round" at 172.141,29.965 h1.52
  text "Top Layer - Bottom Layer" at 190.779,29.965 h1.52
  text "47" at 108.912,26.155 h1.52
  text "10.00mil (0.254mm)" at 125.113,26.155 h1.52
  text "PTH" at 159.291,26.155 h1.52
  text "Round" at 172.141,26.155 h1.52
  text "Top Layer - Bottom Layer" at 190.779,26.155 h1.52
  text "665" at 108.912,22.345 h1.52
  text "12.00mil (0.305mm)" at 125.113,22.345 h1.52
  text "PTH" at 159.291,22.345 h1.52
  text "Round" at 172.141,22.345 h1.52
  text "Top Layer - Bottom Layer" at 190.779,22.345 h1.52
  text "8" at 108.912,18.535 h1.52
  text "20.00mil (0.508mm)" at 125.113,18.535 h1.52
  text "PTH" at 159.291,18.535 h1.52
  text "Round" at 172.141,18.535 h1.52
  text "Top Layer - Bottom Layer" at 190.779,18.535 h1.52
  text "12" at 108.912,14.725 h1.52
  text "40.00mil (1.016mm)" at 125.113,14.725 h1.52
  text "PTH" at 159.291,14.725 h1.52
  text "Round" at 172.141,14.725 h1.52
  text "Top Layer - Bottom Layer" at 190.779,14.725 h1.52
  text "4" at 108.912,10.915 h1.52
  text "125.00mil (3.175mm)" at 125.113,10.915 h1.52
  text "PTH" at 159.291,10.915 h1.52
  text "Round" at 172.141,10.915 h1.52
  text "Top Layer - Bottom Layer" at 190.779,10.915 h1.52
  text "777 Total" at 108.912,7.105 h1.52

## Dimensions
-0.381,0 to -0.381,43.917 on M2 Board Dimensions
-1.905,-24.099 to 23.495,-24.099 on M2 Board Dimensions
-0.381,0 to 76.225,0 on M2 Board Dimensions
